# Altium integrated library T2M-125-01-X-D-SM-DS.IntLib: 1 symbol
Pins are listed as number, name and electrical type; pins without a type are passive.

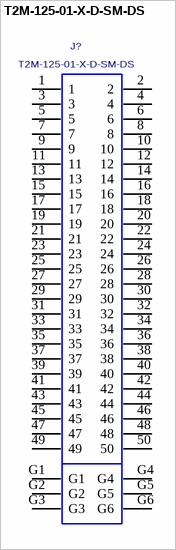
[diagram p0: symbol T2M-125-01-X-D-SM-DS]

## T2M-125-01-X-D-SM-DS
designator J?
2mm Shrouded TerminaL Strip, 60 Pins, Dual Screw Down.; MANUFACTURER: SAMTEC
footprint T2M-125-01-X-D-SM-DS
pins: 1, 2, 3, 4, 5, 6, 7, 8, 9, 10, 11, 12, 13, 14, 15, 16, 17, 18, 19, 20, 21, 22, 23, 24, 25, 26, 27, 28, 29, 30, 31, 32, 33, 34, 35, 36, 37, 38, 39, 40, 41, 42, 43, 44, 45, 46, 47, 48, 49, 50, G1, G2, G3, G4, G5, G6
